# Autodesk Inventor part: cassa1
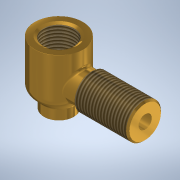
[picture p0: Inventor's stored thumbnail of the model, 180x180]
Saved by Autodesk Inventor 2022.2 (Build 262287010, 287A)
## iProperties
Created: 2014-01
Part Number: cassa1
Document SubType Name: Modeling
Designer: UTENTE
Density: 8.47 g/cm^3
Material: Ottone, Giallo chiaro
Appearance: Ottone - Satinato
Author: UTENTE
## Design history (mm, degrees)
sketch "Schizzo1"
  geometry: C1 r 9 at (0, 0); 1 further point
  constraints: 1 centre point, 1 coincident
extrude "Estrusione1" new body sketch "Schizzo1" distance "d1" = 6; taper "d2" = 0 deg
sketch "Schizzo2"
  geometry: C1 r 9 at (0, 0) reference; C2 r 14.5 at (0, 0)
  constraints: 1 centre point, 1 coincident
extrude "Estrusione2" join sketch "Schizzo2" distance "d4" = 32; taper "d5" = 0 deg
sketch "Schizzo3"
  geometry: C1 r 9 at (0, 0) reference; C2 r 6 at (0, 0)
  constraints: 1 centre point, 1 coincident
extrude "Estrusione3" cut sketch "Schizzo3" distance "d7" = 13; taper "d8" = 0 deg
sketch "Schizzo4"
  geometry: C1 r 6 at (0, 0) reference; C2 r 11 at (0, 0)
  constraints: 1 centre point, 1 coincident
extrude "Estrusione4" cut sketch "Schizzo4" distance "d10" = 11; taper "d11" = 0 deg
hole "Hole1" diameter "d14" = 18.631; stored, may be unused: countersink angle "d18" = 90 deg, drill point angle "d20" = 118 deg; dims "d12" = 10, "d13" = 10, "d15" = 6, "d16" = 4, "d17" = 2, "d19" = 23
chamfer "Smusso1" distance "d21" = 0.5; stored, may be unused: second distance "d22" = 2, angle "d23" = 45 deg
fillet "Raccordo1" dims "d24" = 2
chamfer "Smusso2" distance "d25" = 1.5; stored, may be unused: second distance "d26" = 2, angle "d27" = 30 deg
chamfer "Smusso3" distance "d28" = 5.5; stored, may be unused: second distance "d29" = 2, angle "d30" = 45 deg
fillet "Raccordo2" dims "d31" = 6
fillet "Raccordo3" dims "d32" = 1
sketch "Schizzo5"
  geometry: L1 (-10.816, 38)-(-9.316, 37.134) reference; L2 (-9.316, 37.134)-(-9.316, 24) reference; L3 (-11, 22.025)-(-11, 15) reference; L4 (-9, 13)-(-6.5, 13) reference; L5 (-6.5, 13)-(-6, 12.5) reference; L6 (-6, 12.5)-(-6, 0) reference; L7 (-6, 0)-(-9, 0) reference; L8 (-9, 0)-(-9, 5.586) reference; L9 (-9.293, 6.293)-(-12.743, 9.743) reference; L10 (-14.5, 13.985)-(-14.5, 38) reference; L11 (-14.5, 38)-(-10.816, 38) reference; L12 (9.316, 37.134)-(10.816, 38) reference; L13 (10.816, 38)-(14.5, 38) reference; L14 (14.5, 38)-(14.5, 13.985) reference; L15 (12.743, 9.743)-(9.293, 6.293) reference; L16 (9, 5.586)-(9, 0) reference; L17 (9, 0)-(6, 0) reference; L18 (6, 0)-(6, 12.5) reference; L19 (6, 12.5)-(6.5, 13) reference; L20 (6.5, 13)-(9, 13) reference; L21 (11, 15)-(11, 22.025) reference; L22 (9.316, 24)-(9.316, 37.134) reference; A1 r 2 centre (-9, 22.025) between (-9.316, 24) and (-11, 22.025) reference; A2 r 2 centre (-9, 15) between (-11, 15) and (-9, 13) reference; A3 r 1 centre (-10, 5.586) between (-9, 5.586) and (-9.293, 6.293) reference; A4 r 6 centre (-8.5, 13.985) between (-14.5, 13.985) and (-12.743, 9.743) reference; A5 r 6 centre (8.5, 13.985) between (12.743, 9.743) and (14.5, 13.985) reference; A6 r 1 centre (10, 5.586) between (9.293, 6.293) and (9, 5.586) reference; A7 r 2 centre (9, 15) between (9, 13) and (11, 15) reference; A8 r 2 centre (9, 22.025) between (11, 22.025) and (9.316, 24) reference; 1 further point
  node "Proietta spigoli di taglio1"
node "Piano di lavoro1"
sketch "Schizzo6"
  geometry: C1 r 9 at (0, 19); 1 further point
  constraints: 1 centre point
extrude "Estrusione5" join sketch "Schizzo6" stored distance "d37" = 0; taper "d38" = 0 deg
sketch "Schizzo7"
  geometry: C1 r 9 at (0, 19) reference; C2 r 10.498 at (0, 19); 1 further point
  constraints: 1 centre point, 1 coincident
extrude "Estrusione6" join sketch "Schizzo7" distance "d40" = 32; taper "d41" = 0 deg
hole "Hole2" diameter "d44" = 8; stored, may be unused: countersink angle "d48" = 90 deg, drill point angle "d50" = 118 deg; dims "d42" = 10, "d43" = 10, "d45" = 6, "d46" = 4, "d47" = 2, "d49" = 52
feature "Filettatura1" dims "d51" = 10, "d52" = 0
chamfer "Smusso4" distance "d53" = 1; stored, may be unused: second distance "d54" = 2, angle "d55" = 45 deg
fillet "Raccordo4" dims "d56" = 1.5
chamfer "Smusso5" distance "d57" = 1; stored, may be unused: second distance "d58" = 2, angle "d59" = 30 deg
fillet "Raccordo5" dims "d60" = 1.5
chamfer "Smusso6" distance "d61" = 0.1; stored, may be unused: second distance "d62" = 2, angle "d63" = 45 deg
node "Solido1"
node "Proietta spigoli di taglio2"
other parameters: "d34" = 52
